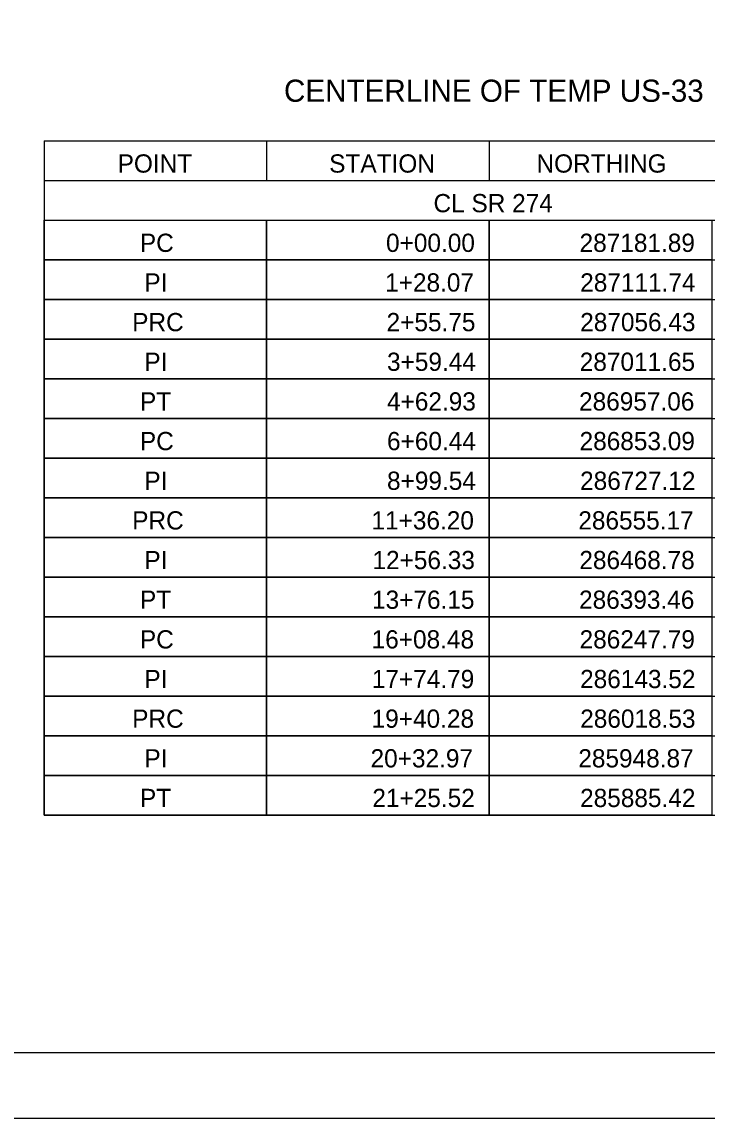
# Model space of a CAD drawing. Extents: x 0 to 34, y 0 to 22.
# Drawn here: x 25 to 30.26, y 0 to 8.41 of the extents above; entities that cross this region are included whole.
import ezdxf

# ---------------------------------------------------------------- set-up
doc = ezdxf.new("R2010")
doc.units = 0
for name, color, linetype in [('SH_Border', 7, 'Continuous'), ('SH_Cut_Line', 7, 'Continuous'), ('SH_Text', 7, 'Continuous')]:
    doc.layers.add(name, color=color, linetype=linetype)

msp = doc.modelspace()

# ---------------------------------------------------------------- linework, layer by layer
at = {"layer": 'SH_Border'}
msp.add_lwpolyline([(1.5, 21.5), (33.5, 21.5), (33.5, 0.5), (1.5, 0.5)], close=True, dxfattribs=at)
at = {"layer": 'SH_Cut_Line'}
msp.add_lwpolyline([(0, 0), (34, 0), (34, 22), (0, 22)], close=True, dxfattribs=at)
at = {"layer": 'SH_Text'}
for p, q in [((25.1691, 7.5), (32, 7.5)), ((25.1691, 7.5), (25.1691, 6.8913)), ((26.8768, 7.5), (26.8768, 7.1957)), ((28.5845, 7.5), (28.5845, 7.1957)), ((25.1691, 7.1957), (32, 7.1957)), ((25.1691, 6.8913), (32, 6.8913)), ((25.1691, 6.8913), (25.1691, 2.3261)), ((26.8768, 6.8913), (26.8768, 2.3261)), ((28.5845, 6.8913), (28.5845, 2.3261)), ((25.1691, 6.587), (32, 6.587)), ((25.1691, 6.2826), (32, 6.2826)), ((25.1691, 5.9783), (32, 5.9783)), ((25.1691, 5.6739), (32, 5.6739)), ((25.1691, 5.3696), (32, 5.3696)), ((25.1691, 5.0652), (32, 5.0652)), ((25.1691, 4.7609), (32, 4.7609)), ((25.1691, 4.4565), (32, 4.4565)), ((25.1691, 4.1522), (32, 4.1522)), ((25.1691, 3.8478), (32, 3.8478)), ((25.1691, 3.5435), (32, 3.5435)), ((25.1691, 3.2391), (32, 3.2391)), ((25.1691, 2.9348), (32, 2.9348)), ((25.1691, 2.6304), (32, 2.6304)), ((25.1691, 2.3261), (32, 2.3261))]:
    msp.add_line(p, q, dxfattribs=at)
for points in [[(25.1691, 6.8913), (26.8768, 6.8913), (26.8768, 6.587), (25.1691, 6.587)], [(26.8768, 6.8913), (28.5845, 6.8913), (28.5845, 6.587), (26.8768, 6.587)], [(28.5845, 6.8913), (30.2923, 6.8913), (30.2923, 6.587), (28.5845, 6.587)], [(25.1691, 6.587), (26.8768, 6.587), (26.8768, 6.2826), (25.1691, 6.2826)], [(26.8768, 6.587), (28.5845, 6.587), (28.5845, 6.2826), (26.8768, 6.2826)], [(28.5845, 6.587), (30.2923, 6.587), (30.2923, 6.2826), (28.5845, 6.2826)], [(25.1691, 6.2826), (26.8768, 6.2826), (26.8768, 5.9783), (25.1691, 5.9783)], [(26.8768, 6.2826), (28.5845, 6.2826), (28.5845, 5.9783), (26.8768, 5.9783)], [(28.5845, 6.2826), (30.2923, 6.2826), (30.2923, 5.9783), (28.5845, 5.9783)], [(25.1691, 5.9783), (26.8768, 5.9783), (26.8768, 5.6739), (25.1691, 5.6739)], [(26.8768, 5.9783), (28.5845, 5.9783), (28.5845, 5.6739), (26.8768, 5.6739)], [(28.5845, 5.9783), (30.2923, 5.9783), (30.2923, 5.6739), (28.5845, 5.6739)], [(25.1691, 5.6739), (26.8768, 5.6739), (26.8768, 5.3696), (25.1691, 5.3696)], [(26.8768, 5.6739), (28.5845, 5.6739), (28.5845, 5.3696), (26.8768, 5.3696)], [(28.5845, 5.6739), (30.2923, 5.6739), (30.2923, 5.3696), (28.5845, 5.3696)], [(25.1691, 5.3696), (26.8768, 5.3696), (26.8768, 5.0652), (25.1691, 5.0652)], [(26.8768, 5.3696), (28.5845, 5.3696), (28.5845, 5.0652), (26.8768, 5.0652)], [(28.5845, 5.3696), (30.2923, 5.3696), (30.2923, 5.0652), (28.5845, 5.0652)], [(25.1691, 5.0652), (26.8768, 5.0652), (26.8768, 4.7609), (25.1691, 4.7609)], [(26.8768, 5.0652), (28.5845, 5.0652), (28.5845, 4.7609), (26.8768, 4.7609)], [(28.5845, 5.0652), (30.2923, 5.0652), (30.2923, 4.7609), (28.5845, 4.7609)], [(25.1691, 4.7609), (26.8768, 4.7609), (26.8768, 4.4565), (25.1691, 4.4565)], [(26.8768, 4.7609), (28.5845, 4.7609), (28.5845, 4.4565), (26.8768, 4.4565)], [(28.5845, 4.7609), (30.2923, 4.7609), (30.2923, 4.4565), (28.5845, 4.4565)], [(25.1691, 4.4565), (26.8768, 4.4565), (26.8768, 4.1522), (25.1691, 4.1522)], [(26.8768, 4.4565), (28.5845, 4.4565), (28.5845, 4.1522), (26.8768, 4.1522)], [(28.5845, 4.4565), (30.2923, 4.4565), (30.2923, 4.1522), (28.5845, 4.1522)], [(25.1691, 4.1522), (26.8768, 4.1522), (26.8768, 3.8478), (25.1691, 3.8478)], [(26.8768, 4.1522), (28.5845, 4.1522), (28.5845, 3.8478), (26.8768, 3.8478)], [(28.5845, 4.1522), (30.2923, 4.1522), (30.2923, 3.8478), (28.5845, 3.8478)], [(25.1691, 3.8478), (26.8768, 3.8478), (26.8768, 3.5435), (25.1691, 3.5435)], [(26.8768, 3.8478), (28.5845, 3.8478), (28.5845, 3.5435), (26.8768, 3.5435)], [(28.5845, 3.8478), (30.2923, 3.8478), (30.2923, 3.5435), (28.5845, 3.5435)], [(25.1691, 3.5435), (26.8768, 3.5435), (26.8768, 3.2391), (25.1691, 3.2391)], [(26.8768, 3.5435), (28.5845, 3.5435), (28.5845, 3.2391), (26.8768, 3.2391)], [(28.5845, 3.5435), (30.2923, 3.5435), (30.2923, 3.2391), (28.5845, 3.2391)], [(25.1691, 3.2391), (26.8768, 3.2391), (26.8768, 2.9348), (25.1691, 2.9348)], [(26.8768, 3.2391), (28.5845, 3.2391), (28.5845, 2.9348), (26.8768, 2.9348)], [(28.5845, 3.2391), (30.2923, 3.2391), (30.2923, 2.9348), (28.5845, 2.9348)], [(25.1691, 2.9348), (26.8768, 2.9348), (26.8768, 2.6304), (25.1691, 2.6304)], [(26.8768, 2.9348), (28.5845, 2.9348), (28.5845, 2.6304), (26.8768, 2.6304)], [(28.5845, 2.9348), (30.2923, 2.9348), (30.2923, 2.6304), (28.5845, 2.6304)], [(25.1691, 2.6304), (26.8768, 2.6304), (26.8768, 2.3261), (25.1691, 2.3261)], [(26.8768, 2.6304), (28.5845, 2.6304), (28.5845, 2.3261), (26.8768, 2.3261)], [(28.5845, 2.6304), (30.2923, 2.6304), (30.2923, 2.3261), (28.5845, 2.3261)]]:
    msp.add_lwpolyline(points, close=True, dxfattribs=at)

# ---------------------------------------------------------------- texts
for s, height, p in [('CENTERLINE OF TEMP US-33 ', 0.17, (27.0099, 7.8)), ('POINT', 0.14, (25.7335, 7.2565)), ('STATION', 0.14, (27.3569, 7.2565)), ('NORTHING', 0.14, (28.9477, 7.2565)), ('CL SR 274', 0.14, (28.1574, 6.9522)), ('PC', 0.14, (25.9043, 6.6478)), ('0+00.00', 0.14, (27.7931, 6.6478)), ('287181.89', 0.14, (29.2783, 6.6478)), ('PI', 0.14, (25.9387, 6.3435)), ('1+28.07', 0.14, (27.7861, 6.3435)), ('287111.74', 0.14, (29.283, 6.3435)), ('PRC', 0.14, (25.8454, 6.0391)), ('2+55.75', 0.14, (27.7973, 6.0391)), ('287056.43', 0.14, (29.283, 6.0391)), ('PI', 0.14, (25.9387, 5.7348)), ('3+59.44', 0.14, (27.8006, 5.7348)), ('287011.65', 0.14, (29.2797, 5.7348)), ('PT', 0.14, (25.905, 5.4304)), ('4+62.93', 0.14, (27.8006, 5.4304)), ('286957.06', 0.14, (29.2743, 5.4304)), ('PC', 0.14, (25.9043, 5.1261)), ('6+60.44', 0.14, (27.8006, 5.1261)), ('286853.09', 0.14, (29.2783, 5.1261)), ('8+99.54', 0.14, (27.8006, 4.8217)), ('286727.12', 0.14, (29.2822, 4.8217)), ('PI', 0.14, (25.9387, 4.8217)), ('PRC', 0.14, (25.8454, 4.5174)), ('11+36.20', 0.14, (27.6814, 4.5174)), ('286555.17', 0.14, (29.2686, 4.5174)), ('PI', 0.14, (25.9387, 4.213)), ('12+56.33', 0.14, (27.6889, 4.213)), ('286468.78', 0.14, (29.2767, 4.213)), ('PT', 0.14, (25.905, 3.9087)), ('13+76.15', 0.14, (27.6856, 3.9087)), ('286393.46', 0.14, (29.2743, 3.9087)), ('PC', 0.14, (25.9043, 3.6043)), ('16+08.48', 0.14, (27.6826, 3.6043)), ('286247.79', 0.14, (29.2783, 3.6043)), ('PI', 0.14, (25.9387, 3.3)), ('17+74.79', 0.14, (27.6841, 3.3)), ('286143.52', 0.14, (29.2822, 3.3)), ('PRC', 0.14, (25.8454, 2.9957)), ('19+40.28', 0.14, (27.6826, 2.9957)), ('286018.53', 0.14, (29.283, 2.9957)), ('PI', 0.14, (25.9387, 2.6913)), ('20+32.97', 0.14, (27.6744, 2.6913)), ('285948.87', 0.14, (29.2686, 2.6913)), ('PT', 0.14, (25.905, 2.387)), ('21+25.52', 0.14, (27.6881, 2.387)), ('285885.42', 0.14, (29.2822, 2.387))]:
    msp.add_text(s, height=height, dxfattribs=at).set_placement(p)

doc.saveas('drawing.dxf')
